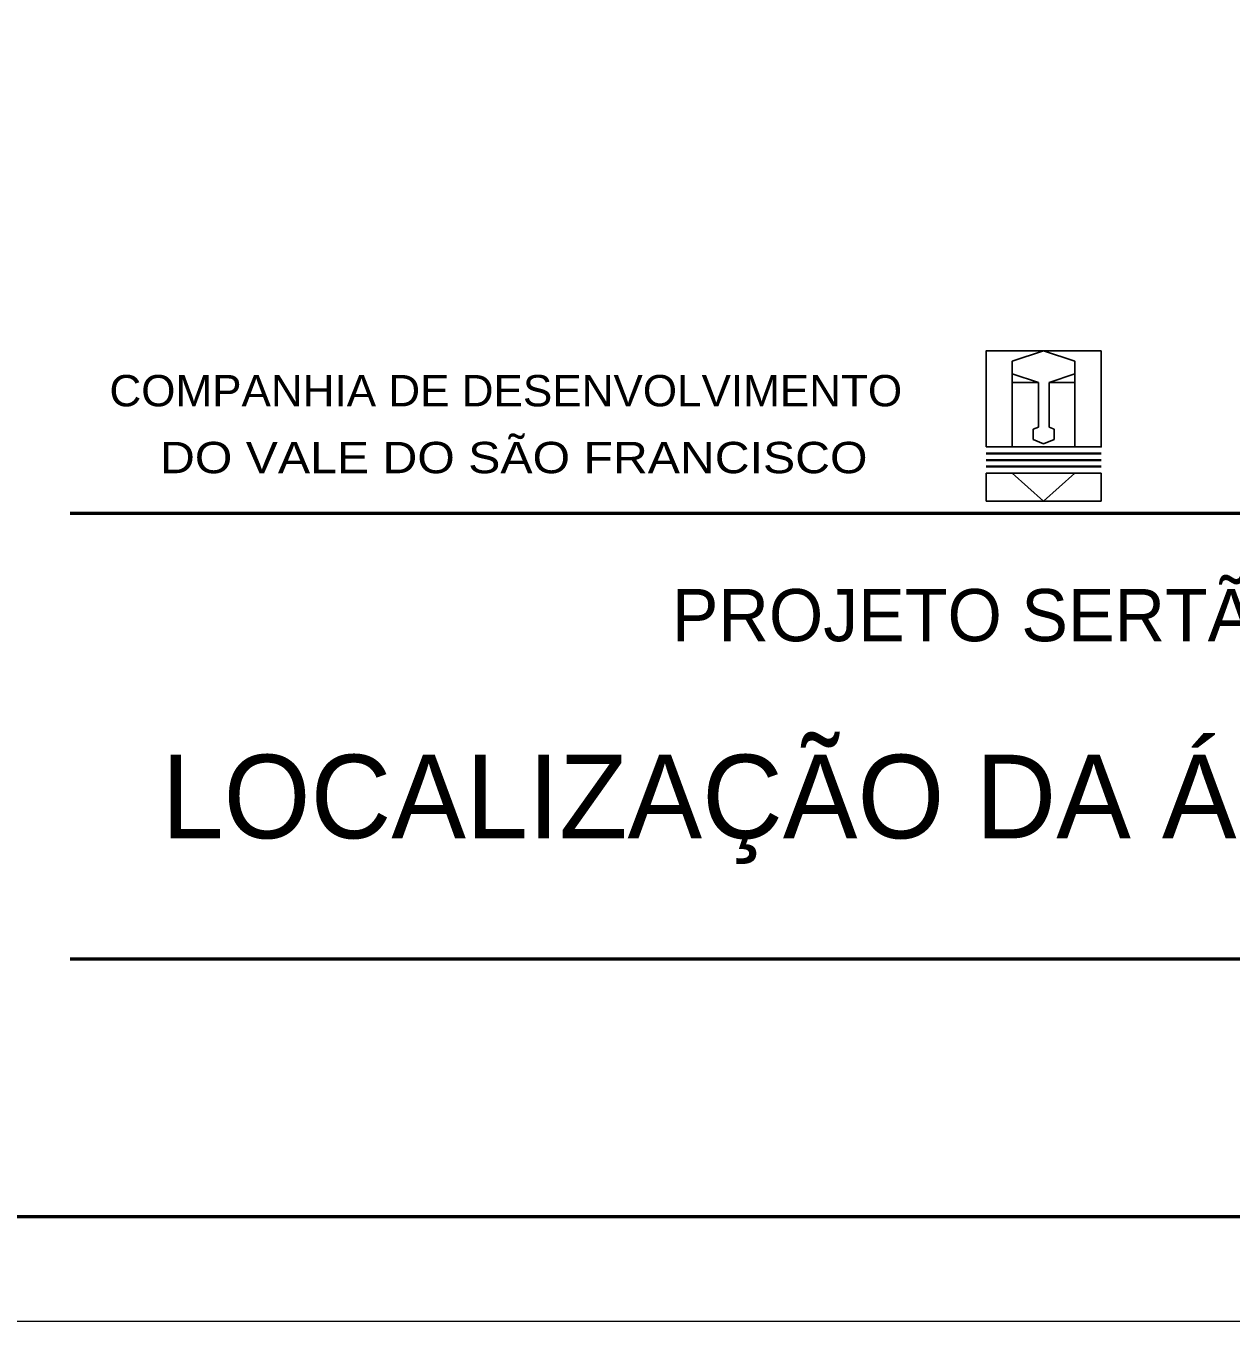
# Model space of a CAD drawing. Extents: x 512883 to 1063249, y 8784064 to 9081064.
# Drawn here: x 947963 to 1005606, y 8784064 to 8846031 of the extents above; entities that cross this region are included whole.
import ezdxf
from ezdxf.enums import TextEntityAlignment as Align

# ---------------------------------------------------------------- set-up
doc = ezdxf.new("R2010")
doc.units = 0
doc.header["$LTSCALE"] = 600
doc.layers.add('1', color=7, linetype='Continuous', lineweight=25)
doc.layers.add('3', color=7, linetype='Continuous', lineweight=25)

msp = doc.modelspace()

# ---------------------------------------------------------------- linework, layer by layer
at = {"layer": '1'}
for p, q in [((995137.1, 8829989.7), (996637.1, 8830489.7)), ((998137.1, 8829989.7), (996637.1, 8830489.7)), ((995137.1, 8825889.7), (995137.1, 8829989.7)), ((998137.1, 8825889.7), (998137.1, 8829989.7)), ((995137.1, 8829389.7), (996397.1, 8828969.7)), ((998137.1, 8829389.7), (996897.1, 8828969.7)), ((996397.1, 8828969.7), (995137.1, 8828969.7)), ((996397.1, 8828969.7), (996397.1, 8826839.7)), ((996897.1, 8828969.7), (996897.1, 8826839.7)), ((996897.1, 8828969.7), (998137.1, 8828969.7)), ((996397.1, 8826839.7), (996137.1, 8826739.7)), ((996137.1, 8826739.7), (996137.1, 8826239.7)), ((996897.1, 8826839.7), (997137.1, 8826739.7)), ((997137.1, 8826739.7), (997137.1, 8826239.7)), ((996637.1, 8826029.7), (996137.1, 8826239.7)), ((996637.1, 8826029.7), (997137.1, 8826239.7)), ((993897.1, 8824629.7), (999397.1, 8824629.7)), ((993897.1, 8824629.7), (993897.1, 8823289.7)), ((999397.1, 8824629.7), (999397.1, 8823289.7)), ((993897.1, 8823289.7), (999397.1, 8823289.7))]:
    msp.add_line(p, q, dxfattribs=at)
at = {"layer": '1', "lineweight": 35}
for p, q in [((993897.1, 8825569.7), (999397.1, 8825569.7)), ((993897.1, 8825259.7), (999397.1, 8825259.7)), ((993897.1, 8824949.7), (999397.1, 8824949.7))]:
    msp.add_line(p, q, dxfattribs=at)
at = {"layer": '1', "lineweight": 53}
for p, q in [((950077.1, 8822719.7), (1054757.1, 8822719.7)), ((950077.1, 8801399.7), (1054757.1, 8801399.7))]:
    msp.add_line(p, q, dxfattribs=at)
at = {"layer": '1', "lineweight": 13}
for points in [[(512883.1, 8784063.9), (1063248.6, 8784063.9), (1063248.6, 9081063.9), (512883.1, 9081063.9)], [(537883.1, 9076063.9), (1058248.6, 9076063.9), (1058248.6, 8789063.9), (537883.1, 8789063.9)]]:
    msp.add_lwpolyline(points, close=True, dxfattribs=at)
at = {"layer": '1', "lineweight": 53}
msp.add_lwpolyline([(537883.1, 8789063.9), (1058248.6, 8789063.9), (1058248.6, 9076063.9), (537883.1, 9076063.9)], close=True, dxfattribs=at)
at = {"layer": '1'}
msp.add_lwpolyline([(537883.1, 9076063.9), (1058248.6, 9076063.9), (1058248.6, 8789063.9), (537883.1, 8789063.9)], close=True, dxfattribs=at)
for points in [[(993897.1, 8825889.7), (999397.1, 8825889.7), (999397.1, 8830489.7)], [(993897.1, 8825889.7), (993897.1, 8830489.7), (999397.1, 8830489.7)], [(995137.1, 8824629.7), (996637.1, 8823289.7), (998137.1, 8824629.7)]]:
    msp.add_lwpolyline(points, dxfattribs=at)
at = {"layer": '3'}
msp.add_lwpolyline([(537883.1, 9076063.9), (1058248.6, 9076063.9), (1058248.6, 8789063.9), (537883.1, 8789063.9)], close=True, dxfattribs=at)

# ---------------------------------------------------------------- texts
at = {"layer": '1'}
for s, width, p in [('COMPANHIA DE DESENVOLVIMENTO', 1.05, (951957.1, 8827829.7)), ('DO VALE DO SÃO FRANCISCO', 1.15, (954377.1, 8824629.7))]:
    msp.add_text(s, height=1500, dxfattribs=dict(at, width=width)).set_placement(p)
msp.add_text('PROJETO SERTÃO ALAGOANO', height=2500, dxfattribs=at).set_placement((1003932.6, 8816589.7), align=Align.CENTER)
msp.add_text('LOCALIZAÇÃO DA ÁREA NO ESTADO', height=4000, dxfattribs=at).set_placement((954442.2, 8807162))

doc.saveas('drawing.dxf')
